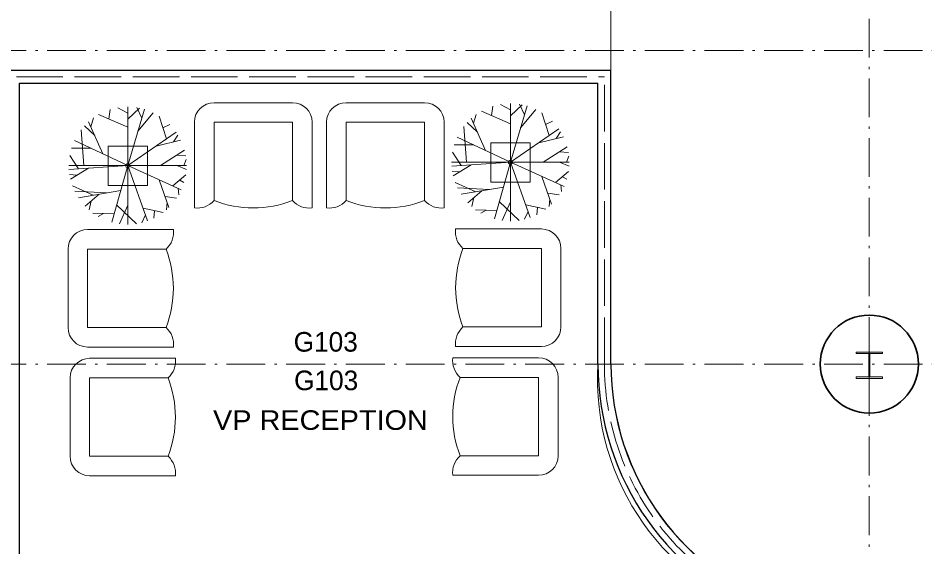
# Model space of a CAD drawing. Extents: x -118748 to -117136, y -118748 to -117596.
# Drawn here: x -118268.3 to -118046.3, y -118460 to -118330.4 of the extents above; entities that cross this region are included whole.
import ezdxf
from ezdxf.enums import TextEntityAlignment as Align

# ---------------------------------------------------------------- set-up
doc = ezdxf.new("R2010")
doc.units = 0
doc.header["$LTSCALE"] = 1.9
doc.header["$PDMODE"] = 32
doc.header["$PDSIZE"] = 0.95
doc.linetypes.add('DOT_DASHED', pattern=[7.7, 5, -1.2, 0.3, -1.2])
doc.linetypes.add('LONG_DASHED', pattern=[7.5, 6, -1.5])
for name, color, linetype, lineweight in [('10', 7, 'DOT_DASHED', 13), ('12', 7, 'Continuous', 13), ('15', 7, 'Continuous', 13), ('23', 7, 'Continuous', 25), ('30', 7, 'Continuous', 13), ('5', 7, 'Continuous', 13), ('6', 7, 'Continuous', 13), ('60', 7, 'LONG_DASHED', 13), ('9', 7, 'Continuous', 35)]:
    doc.layers.add(name, color=color, linetype=linetype, lineweight=lineweight)
doc.layers.add('53', color=7, linetype='Continuous')

msp = doc.modelspace()

# ---------------------------------------------------------------- linework, layer by layer
at = {"layer": '10'}
for p, q in [((-118059.921, -117628.339), (-118059.921, -118698.41)), ((-118641.571, -118338.41), (-117285.521, -118338.41)), ((-118641.571, -118415.21), (-117285.521, -118415.21))]:
    msp.add_line(p, q, dxfattribs=at)
at = {"layer": '12'}
msp.add_lwpolyline([(-118063.104, -118418.762), (-118056.688, -118418.762), (-118056.688, -118418.366), (-118059.772, -118418.366), (-118059.772, -118412.662), (-118056.688, -118412.662), (-118056.688, -118412.266), (-118063.104, -118412.266), (-118063.104, -118412.662), (-118060.02, -118412.662), (-118060.02, -118418.366), (-118063.104, -118418.366)], close=True, dxfattribs=at)
at = {"layer": '12', "lineweight": 35}
msp.add_circle((-118059.921, -118415.21), 12, dxfattribs=at)
at = {"layer": '15'}
for p, q in [((-118201.132, -118351.163), (-118220.332, -118351.163)), ((-118168.798, -118351.163), (-118187.998, -118351.163)), ((-118225.132, -118355.963), (-118225.132, -118376.948)), ((-118196.332, -118376.948), (-118196.332, -118355.963)), ((-118192.798, -118355.963), (-118192.798, -118376.948)), ((-118163.998, -118376.948), (-118163.998, -118355.963)), ((-118140.202, -118382.115), (-118161.188, -118382.115)), ((-118230.298, -118382.246), (-118251.284, -118382.246)), ((-118256.084, -118387.046), (-118256.084, -118406.246)), ((-118135.402, -118406.115), (-118135.402, -118386.914)), ((-118161.188, -118410.914), (-118140.202, -118410.914)), ((-118251.284, -118411.046), (-118230.298, -118411.046)), ((-118229.802, -118413.807), (-118250.788, -118413.807)), ((-118140.902, -118413.675), (-118161.887, -118413.675)), ((-118255.588, -118418.607), (-118255.588, -118437.807)), ((-118136.102, -118437.675), (-118136.102, -118418.475)), ((-118250.788, -118442.607), (-118229.802, -118442.607)), ((-118161.887, -118442.475), (-118140.902, -118442.475))]:
    msp.add_line(p, q, dxfattribs=at)
for points in [[(-118201.132, -118375.163), (-118201.132, -118355.963), (-118220.332, -118355.963), (-118220.332, -118375.163)], [(-118168.798, -118375.163), (-118168.798, -118355.963), (-118187.998, -118355.963), (-118187.998, -118375.163)], [(-118232.084, -118387.046), (-118251.284, -118387.046), (-118251.284, -118406.246), (-118232.084, -118406.246)], [(-118159.402, -118406.115), (-118140.202, -118406.115), (-118140.202, -118386.914), (-118159.402, -118386.914)], [(-118231.588, -118418.607), (-118250.788, -118418.607), (-118250.788, -118437.807), (-118231.588, -118437.807)], [(-118160.102, -118437.675), (-118140.902, -118437.675), (-118140.902, -118418.475), (-118160.102, -118418.475)]]:
    msp.add_lwpolyline(points, dxfattribs=at)
for centre, radius, start, end in [((-118220.332, -118355.963), 4.8, 90, 180), ((-118201.132, -118355.963), 4.8, 360, 90), ((-118187.998, -118355.963), 4.8, 90, 180), ((-118168.798, -118355.963), 4.8, 360, 90), ((-118224.437, -118371.471), 5.521, 262.77334, 318.03706), ((-118210.732, -118350.249), 26.699, 248.92678, 291.07322), ((-118197.026, -118371.471), 5.521, 221.96294, 277.22666), ((-118192.104, -118371.471), 5.521, 262.77334, 318.03706), ((-118178.398, -118350.249), 26.699, 248.92678, 291.07322), ((-118164.693, -118371.471), 5.521, 221.96294, 277.22666), ((-118155.71, -118382.809), 5.521, 172.77334, 228.03706), ((-118140.202, -118386.914), 4.8, 360, 90), ((-118251.284, -118387.046), 4.8, 90, 180), ((-118235.775, -118382.94), 5.521, 311.96294, 7.22666), ((-118256.997, -118396.646), 26.699, 338.92678, 21.07322), ((-118134.488, -118396.515), 26.699, 158.92678, 201.07321), ((-118251.284, -118406.246), 4.8, 180, 270), ((-118235.775, -118410.351), 5.521, 352.77334, 48.03706), ((-118155.71, -118410.22), 5.521, 131.96294, 187.22666), ((-118140.202, -118406.115), 4.8, 270, 0), ((-118250.788, -118418.607), 4.8, 90, 180), ((-118235.28, -118414.501), 5.521, 311.96294, 7.22666), ((-118156.41, -118414.37), 5.521, 172.77334, 228.03706), ((-118140.902, -118418.475), 4.8, 0, 90), ((-118256.502, -118428.207), 26.699, 338.92678, 21.07322), ((-118135.188, -118428.075), 26.699, 158.92678, 201.07322), ((-118250.788, -118437.807), 4.8, 180, 270), ((-118235.28, -118441.912), 5.521, 352.77334, 48.03706), ((-118156.41, -118441.781), 5.521, 131.96294, 187.22666), ((-118140.902, -118437.675), 4.8, 270, 0)]:
    msp.add_arc(centre, radius, start, end, dxfattribs=at)
at = {"layer": '23'}
for p, q in [((-118272.721, -118343.21), (-118123.175, -118343.21)), ((-118123.175, -118415.21), (-118123.175, -118343.21)), ((-118267.921, -118487.21), (-118267.921, -118346.41)), ((-118267.921, -118346.41), (-118126.375, -118346.41)), ((-118126.375, -118415.222), (-118126.375, -118346.41))]:
    msp.add_line(p, q, dxfattribs=at)
for radius, start, end in [(66.454, 180, 180.01043), (66.454, 180.01043, 250.28947), (63.254, 180, 252.31759)]:
    msp.add_arc((-118059.921, -118415.21), radius, start, end, dxfattribs=at)
at = {"layer": '30'}
for p, q in [((-118246.078, -118355.162), (-118245.753, -118352.844)), ((-118241.48, -118353.759), (-118243.918, -118352.404)), ((-118241.48, -118380.996), (-118241.48, -118352.196)), ((-118241.48, -118355.193), (-118238.572, -118352.492)), ((-118241.48, -118366.596), (-118237.394, -118352.788)), ((-118238.043, -118354.98), (-118239.229, -118352.373)), ((-118147.795, -118356.336), (-118154.9, -118353.241)), ((-118152.394, -118354.333), (-118152.068, -118352.015)), ((-118147.795, -118352.929), (-118150.233, -118351.574)), ((-118147.795, -118380.167), (-118147.795, -118351.367)), ((-118147.795, -118354.364), (-118144.887, -118351.663)), ((-118147.795, -118365.767), (-118143.709, -118351.958)), ((-118144.358, -118354.151), (-118145.544, -118351.544)), ((-118145.3, -118357.335), (-118141.53, -118352.801)), ((-118250.501, -118357.042), (-118249.839, -118354.871)), ((-118241.48, -118357.165), (-118248.585, -118354.07)), ((-118238.985, -118358.164), (-118235.214, -118353.63)), ((-118232.005, -118360.055), (-118233.751, -118354.445)), ((-118153.856, -118362.885), (-118157.355, -118354.998)), ((-118156.816, -118356.213), (-118156.155, -118354.041)), ((-118138.32, -118359.226), (-118140.066, -118353.616)), ((-118249.553, -118359.179), (-118252.047, -118356.813)), ((-118247.541, -118363.714), (-118251.04, -118355.827)), ((-118232.841, -118357.368), (-118231.174, -118356.538)), ((-118158.517, -118365.767), (-118159.197, -118356.971)), ((-118155.868, -118358.35), (-118158.362, -118355.984)), ((-118147.795, -118365.767), (-118135.944, -118357.586)), ((-118139.157, -118356.539), (-118137.49, -118355.709)), ((-118252.201, -118366.596), (-118252.882, -118357.8)), ((-118241.48, -118366.596), (-118229.629, -118358.415)), ((-118230.26, -118360.77), (-118229.179, -118359.108)), ((-118147.795, -118365.767), (-118160.8, -118359.584)), ((-118140.858, -118360.978), (-118134.822, -118359.516)), ((-118136.576, -118359.941), (-118135.495, -118358.279)), ((-118241.48, -118366.596), (-118254.485, -118360.413)), ((-118234.543, -118361.807), (-118228.507, -118360.345)), ((-118156.735, -118361.516), (-118161.554, -118361.519)), ((-118139.727, -118365.767), (-118133.903, -118361.975)), ((-118253.493, -118367.405), (-118255.668, -118364.134)), ((-118250.42, -118362.345), (-118255.239, -118362.348)), ((-118233.412, -118366.596), (-118227.588, -118362.804)), ((-118229.459, -118364.022), (-118227.281, -118364.199)), ((-118159.809, -118366.575), (-118161.983, -118363.305)), ((-118135.774, -118363.193), (-118133.596, -118363.37)), ((-118134.062, -118365.767), (-118133.475, -118364.252)), ((-118227.746, -118366.596), (-118227.16, -118365.081)), ((-118133.395, -118365.767), (-118162.195, -118365.767)), ((-118147.795, -118365.767), (-118162.163, -118366.734)), ((-118157.381, -118366.412), (-118161.815, -118369.053)), ((-118147.795, -118365.767), (-118151.694, -118379.629)), ((-118147.795, -118365.767), (-118134.66, -118371.668)), ((-118147.795, -118365.767), (-118142.911, -118379.313)), ((-118135.783, -118365.767), (-118133.426, -118366.703)), ((-118227.08, -118366.596), (-118255.88, -118366.596)), ((-118241.48, -118366.596), (-118255.847, -118367.563)), ((-118253.889, -118368.922), (-118255.718, -118368.75)), ((-118251.066, -118367.241), (-118255.5, -118369.882)), ((-118241.48, -118366.596), (-118245.379, -118380.458)), ((-118241.48, -118366.596), (-118228.345, -118372.497)), ((-118241.48, -118366.596), (-118236.596, -118380.142)), ((-118229.467, -118366.596), (-118227.11, -118367.532)), ((-118160.204, -118368.093), (-118162.033, -118367.92)), ((-118136.747, -118370.731), (-118133.577, -118368.047)), ((-118233.741, -118370.073), (-118231.369, -118376.849)), ((-118230.432, -118371.56), (-118227.262, -118368.876)), ((-118228.737, -118370.125), (-118227.694, -118370.756)), ((-118156.225, -118372.993), (-118161.313, -118370.729)), ((-118140.057, -118369.244), (-118137.685, -118376.02)), ((-118135.052, -118369.296), (-118134.009, -118369.927)), ((-118249.909, -118373.822), (-118254.998, -118371.558)), ((-118246.655, -118373.266), (-118254.452, -118372.848)), ((-118243.189, -118372.673), (-118253.553, -118374.445)), ((-118229.123, -118372.148), (-118228.973, -118373.732)), ((-118152.97, -118372.437), (-118160.767, -118372.019)), ((-118149.505, -118371.844), (-118159.868, -118373.616)), ((-118154.795, -118372.749), (-118158.214, -118375.707)), ((-118135.438, -118371.319), (-118135.288, -118372.903)), ((-118248.48, -118373.578), (-118251.899, -118376.536)), ((-118250.411, -118375.248), (-118250.937, -118377.455)), ((-118232.304, -118374.178), (-118229.509, -118374.6)), ((-118156.726, -118374.419), (-118157.252, -118376.626)), ((-118150.506, -118375.406), (-118145.652, -118380.006)), ((-118147.795, -118375.448), (-118149.797, -118380.027)), ((-118138.62, -118373.348), (-118135.825, -118373.771)), ((-118138.115, -118374.791), (-118138.298, -118376.59)), ((-118244.191, -118376.235), (-118239.337, -118380.835)), ((-118241.48, -118376.277), (-118243.481, -118380.856)), ((-118237.713, -118377.045), (-118232.793, -118378.081)), ((-118234.873, -118377.643), (-118235.04, -118379.475)), ((-118231.8, -118375.62), (-118231.982, -118377.419)), ((-118151.116, -118377.573), (-118156.295, -118377.39)), ((-118153.711, -118377.482), (-118155.02, -118378.223)), ((-118144.028, -118376.216), (-118139.109, -118377.251)), ((-118141.189, -118376.814), (-118141.355, -118378.646)), ((-118244.801, -118378.402), (-118249.98, -118378.219)), ((-118247.396, -118378.311), (-118248.705, -118379.052)), ((-118237.129, -118378.665), (-118238.021, -118380.574)), ((-118143.444, -118377.836), (-118144.336, -118379.745))]:
    msp.add_line(p, q, dxfattribs=at)
for points in [[(-118236.632, -118371.439), (-118246.232, -118371.439), (-118246.232, -118361.839), (-118236.632, -118361.839)], [(-118142.947, -118370.61), (-118152.547, -118370.61), (-118152.547, -118361.01), (-118142.947, -118361.01)]]:
    msp.add_lwpolyline(points, close=True, dxfattribs=at)
for p in [(-118241.48, -118366.596), (-118147.795, -118365.767)]:
    msp.add_point(p, dxfattribs=at)
at = {"layer": '5'}
for points in [[(-118123.174, -118415.21), (-118123.175, -118343.21), (-118272.721, -118343.21), (-118496.721, -118343.21), (-118496.721, -118333.61), (-118496.721, -118301.61), (-118496.721, -118295.21), (-118463.121, -118295.21), (-118123.171, -118295.21), (-118123.171, -118184.81)], [(-118082.334, -118477.77), (-118082.358, -118554.958), (-118084.029, -118563.732), (-118084.594, -118565.229), (-118088.804, -118573.214), (-118089.789, -118574.475), (-118096.188, -118580.843), (-118097.504, -118581.753), (-118105.509, -118585.926), (-118107.036, -118586.403), (-118115.921, -118588.001), (-118301.521, -118588.01), (-118301.521, -118520.81), (-118301.521, -118487.21), (-118267.921, -118487.21), (-118267.921, -118346.41)], [(-118267.921, -118346.41), (-118126.375, -118346.41), (-118126.374, -118415.222)]]:
    msp.add_lwpolyline(points, dxfattribs=at)
for radius, start, end in [(66.454, 180.01043, 250.28947), (63.254, 180, 252.31759)]:
    msp.add_arc((-118059.921, -118415.21), radius, start, end, dxfattribs=at)
at = {"layer": '6'}
msp.add_line((-118123.175, -118415.21), (-118123.171, -118184.81), dxfattribs=at)
msp.add_lwpolyline([(-118496.721, -118343.21), (-118123.171, -118343.21), (-118123.171, -118295.21), (-118496.721, -118295.21)], close=True, dxfattribs=at)
msp.add_lwpolyline([(-118496.721, -118636.01), (-118496.721, -118487.21), (-118301.521, -118487.21), (-118267.921, -118487.21), (-118267.921, -118346.41), (-118126.375, -118346.41), (-118126.374, -118415.21)], dxfattribs=at)
for centre, radius, start, end in [((-118065.048, -118418.819), 61.432, 176.63131, 253.65813), ((-118060.069, -118415.317), 63.106, 179.90204, 252.41563)]:
    msp.add_arc(centre, radius, start, end, dxfattribs=at)
at = {"layer": '60'}
for p in [(-118496.721, -118344.81), (-118124.774, -118415.21)]:
    msp.add_line(p, (-118124.774, -118344.81), dxfattribs=at)
msp.add_arc((-118059.921, -118415.21), 64.854, 180, 251.28157, dxfattribs=at)

# ---------------------------------------------------------------- texts
at = {"layer": '53', "width": 1.1}
msp.add_text('VP RECEPTION', height=4.8, dxfattribs=at).set_placement((-118220.581, -118431.338))
at = {"layer": '9'}
for p in [(-118192.991, -118412.164), (-118192.893, -118421.613)]:
    msp.add_text('G103', height=4.8, dxfattribs=at).set_placement(p, align=Align.CENTER)

doc.saveas('drawing.dxf')
